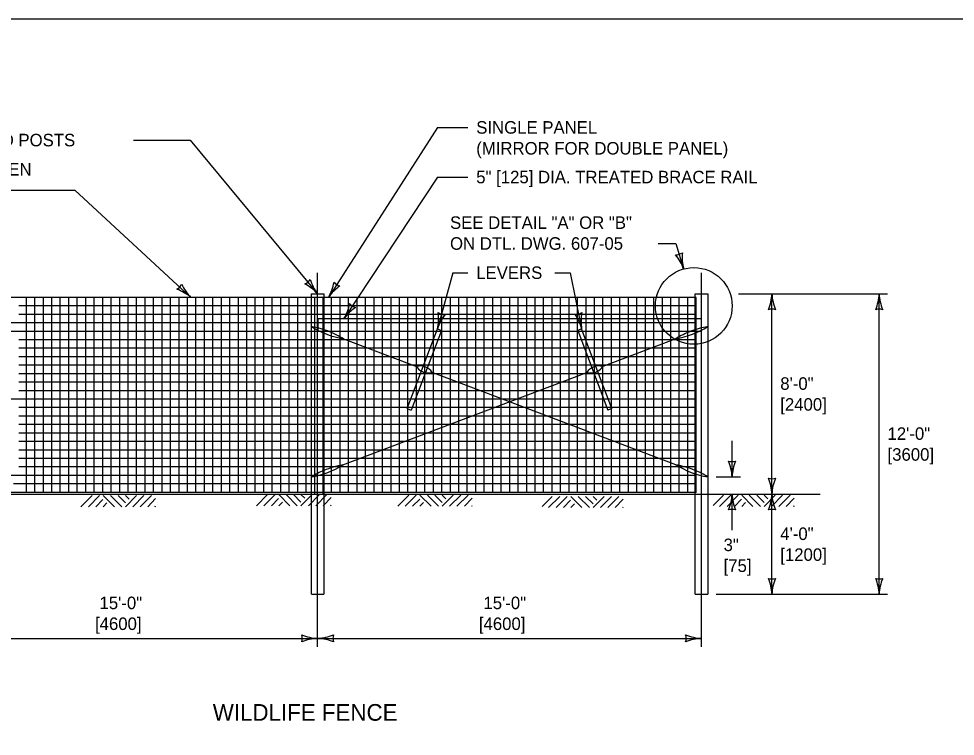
# Model space of a CAD drawing. Extents: x 49991.4 to 50021, y 49987.6 to 50011.4.
# Drawn here: x 50005.896 to 50010.385, y 49995.56 to 49998.999 of the extents above; entities that cross this region are included whole.
import ezdxf

# ---------------------------------------------------------------- set-up
doc = ezdxf.new("R2010")
doc.units = 0
for name, color, linetype in [('Level 1', 7, 'Continuous'), ('Level 2', 7, 'Continuous'), ('Level 3', 7, 'Continuous'), ('Level 4', 7, 'Continuous'), ('Level 5', 7, 'Continuous')]:
    doc.layers.add(name, color=color, linetype=linetype)

msp = doc.modelspace()

# ---------------------------------------------------------------- linework, layer by layer
at = {"layer": 'Level 1'}
for p, q in [((50007.299, 49996.7205), (50007.299, 49997.6806)), ((50007.299, 49997.6806), (50007.359, 49997.6806)), ((50007.359, 49997.6806), (50007.359, 49996.7205)), ((50009.1391, 49997.6806), (50009.1991, 49997.6806)), ((50009.1391, 49996.7205), (50009.1391, 49997.6806)), ((50009.1991, 49997.6806), (50009.1991, 49996.7205)), ((50009.1438, 49997.6633), (50005.1131, 49997.6633)), ((50005.9331, 49996.7285), (50005.9331, 49997.6633)), ((50005.9737, 49996.7285), (50005.9737, 49997.6633)), ((50006.0144, 49996.7285), (50006.0144, 49997.6633)), ((50006.055, 49996.7285), (50006.055, 49997.6633)), ((50006.0957, 49996.7285), (50006.0957, 49997.6633)), ((50006.1363, 49996.7285), (50006.1363, 49997.6633)), ((50006.177, 49996.7285), (50006.177, 49997.6633)), ((50006.2176, 49996.7285), (50006.2176, 49997.6633)), ((50006.2582, 49996.7285), (50006.2582, 49997.6633)), ((50006.2989, 49996.7285), (50006.2989, 49997.6633)), ((50006.3395, 49996.7285), (50006.3395, 49997.6633)), ((50006.3802, 49996.7285), (50006.3802, 49997.6633)), ((50006.4208, 49996.7285), (50006.4208, 49997.6633)), ((50006.4614, 49996.7285), (50006.4614, 49997.6633)), ((50006.5021, 49996.7285), (50006.5021, 49997.6633)), ((50006.5427, 49996.7285), (50006.5427, 49997.6633)), ((50006.5834, 49996.7285), (50006.5834, 49997.6633)), ((50006.624, 49996.7285), (50006.624, 49997.6633)), ((50006.6647, 49996.7285), (50006.6647, 49997.6633)), ((50006.7053, 49996.7285), (50006.7053, 49997.6633)), ((50006.7459, 49996.7285), (50006.7459, 49997.6633)), ((50006.7866, 49996.7285), (50006.7866, 49997.6633)), ((50006.8272, 49996.7285), (50006.8272, 49997.6633)), ((50006.8679, 49996.7285), (50006.8679, 49997.6633)), ((50006.9085, 49996.7285), (50006.9085, 49997.6633)), ((50006.9492, 49996.7285), (50006.9492, 49997.6633)), ((50006.9898, 49996.7285), (50006.9898, 49997.6633)), ((50007.0304, 49996.7285), (50007.0304, 49997.6633)), ((50007.0711, 49996.7285), (50007.0711, 49997.6633)), ((50007.1117, 49996.7285), (50007.1117, 49997.6633)), ((50007.1524, 49996.7285), (50007.1524, 49997.6633)), ((50007.193, 49996.7285), (50007.193, 49997.6633)), ((50007.2336, 49996.7285), (50007.2336, 49997.6633)), ((50007.2743, 49996.7285), (50007.2743, 49997.6633)), ((50007.3149, 49996.7205), (50007.3149, 49997.6633)), ((50007.3556, 49996.7205), (50007.3556, 49997.6633)), ((50007.3962, 49996.7285), (50007.3962, 49997.6633)), ((50007.4369, 49996.7285), (50007.4369, 49997.6633)), ((50007.4775, 49996.7285), (50007.4775, 49997.6633)), ((50007.5181, 49996.7285), (50007.5181, 49997.6633)), ((50007.5588, 49996.7285), (50007.5588, 49997.6633)), ((50007.5994, 49996.7285), (50007.5994, 49997.6633)), ((50007.6401, 49996.7285), (50007.6401, 49997.6633)), ((50007.6807, 49996.7285), (50007.6807, 49997.6633)), ((50007.7214, 49996.7285), (50007.7214, 49997.6633)), ((50007.762, 49996.7285), (50007.762, 49997.6633)), ((50007.8026, 49996.7285), (50007.8026, 49997.6633)), ((50007.8433, 49996.7285), (50007.8433, 49997.6633)), ((50007.8839, 49996.7285), (50007.8839, 49997.6633)), ((50007.9246, 49996.7285), (50007.9246, 49997.6633)), ((50007.9652, 49996.7285), (50007.9652, 49997.6633)), ((50008.0058, 49996.7285), (50008.0058, 49997.6633)), ((50008.0465, 49996.7285), (50008.0465, 49997.6633)), ((50008.0871, 49996.7285), (50008.0871, 49997.6633)), ((50008.1278, 49996.7285), (50008.1278, 49997.6633)), ((50008.1684, 49996.7285), (50008.1684, 49997.6633)), ((50008.2091, 49996.7285), (50008.2091, 49997.6633)), ((50008.2497, 49996.7285), (50008.2497, 49997.6633)), ((50008.2903, 49996.7285), (50008.2903, 49997.6633)), ((50008.331, 49996.7285), (50008.331, 49997.6633)), ((50008.3716, 49996.7285), (50008.3716, 49997.6633)), ((50008.4123, 49996.7285), (50008.4123, 49997.6633)), ((50008.4529, 49996.7285), (50008.4529, 49997.6633)), ((50008.4935, 49996.7285), (50008.4935, 49997.6633)), ((50008.5342, 49996.7285), (50008.5342, 49997.6633)), ((50008.5748, 49996.7285), (50008.5748, 49997.6633)), ((50008.6155, 49996.7285), (50008.6155, 49997.6633)), ((50008.6561, 49996.7285), (50008.6561, 49997.6633)), ((50008.6968, 49996.7285), (50008.6968, 49997.6633)), ((50008.7374, 49996.7285), (50008.7374, 49997.6633)), ((50008.778, 49996.7285), (50008.778, 49997.6633)), ((50008.8187, 49996.7285), (50008.8187, 49997.6633)), ((50008.8593, 49996.7285), (50008.8593, 49997.6633)), ((50008.9, 49996.7285), (50008.9, 49997.6633)), ((50008.9406, 49996.7285), (50008.9406, 49997.6633)), ((50008.9813, 49996.7285), (50008.9813, 49997.6633)), ((50009.0219, 49996.7285), (50009.0219, 49997.6633)), ((50009.0625, 49996.7285), (50009.0625, 49997.6633)), ((50009.1032, 49996.7285), (50009.1032, 49997.6633)), ((50009.1438, 49996.7285), (50009.1438, 49997.6633)), ((50009.1438, 49997.6227), (50005.8964, 49997.6227)), ((50005.9058, 49997.5413), (50005.1225, 49997.5413)), ((50009.1438, 49997.582), (50005.8964, 49997.582)), ((50009.1438, 49997.5414), (50005.9059, 49997.5414)), ((50009.1391, 49997.5607), (50007.359, 49997.5607)), ((50007.3299, 49997.5007), (50005.1131, 49997.5007)), ((50009.1391, 49997.5007), (50007.359, 49997.5007)), ((50007.7587, 49997.1305), (50007.9035, 49997.5125)), ((50007.9222, 49997.5054), (50007.7774, 49997.1234)), ((50007.9035, 49997.5125), (50007.9222, 49997.5054)), ((50008.5945, 49997.5125), (50008.5758, 49997.5054)), ((50008.5758, 49997.5054), (50008.7206, 49997.1234)), ((50008.7393, 49997.1305), (50008.5945, 49997.5125)), ((50009.1438, 49997.4601), (50005.8964, 49997.4601)), ((50007.4529, 49997.4649), (50007.8025, 49997.3323)), ((50009.046, 49997.4653), (50008.6955, 49997.3324)), ((50009.1438, 49997.4194), (50005.8964, 49997.4194)), ((50009.1438, 49997.3788), (50005.8964, 49997.3788)), ((50009.1438, 49997.3382), (50005.8964, 49997.3382)), ((50009.1438, 49997.2975), (50005.8964, 49997.2975)), ((50007.4501, 49996.8602), (50008.6195, 49997.3037)), ((50009.0458, 49996.8611), (50007.8785, 49997.3035)), ((50009.1438, 49997.2569), (50005.8964, 49997.2569)), ((50009.1438, 49997.2162), (50005.8964, 49997.2162)), ((50006.8359, 49997.1756), (50005.1337, 49997.1756)), ((50009.1438, 49997.1756), (50006.8359, 49997.1756)), ((50009.1438, 49997.135), (50005.8964, 49997.135)), ((50009.1438, 49997.0943), (50005.8964, 49997.0943)), ((50007.7587, 49997.1305), (50007.7774, 49997.1234)), ((50008.7393, 49997.1305), (50008.7206, 49997.1234)), ((50009.1438, 49997.0537), (50005.8964, 49997.0537)), ((50009.1438, 49997.013), (50005.8964, 49997.013)), ((50009.1438, 49996.9724), (50005.8964, 49996.9724)), ((50009.1438, 49996.9317), (50005.8964, 49996.9317)), ((50009.1438, 49996.8911), (50005.8964, 49996.8911)), ((50009.1438, 49996.8505), (50005.8964, 49996.8505)), ((50005.9294, 49996.8098), (50005.1463, 49996.8098)), ((50009.1438, 49996.8098), (50005.9295, 49996.8098)), ((50009.1438, 49996.7692), (50005.8709, 49996.7692)), ((50009.1438, 49996.7285), (50005.1131, 49996.7285)), ((50005.1131, 49996.7205), (50009.738, 49996.7205)), ((50006.1948, 49996.6602), (50006.2481, 49996.7134)), ((50006.1948, 49996.6602), (50006.2481, 49996.7134)), ((50006.2303, 49996.6602), (50006.2836, 49996.7134)), ((50006.2303, 49996.6602), (50006.2836, 49996.7134)), ((50006.2658, 49996.6602), (50006.3002, 49996.6945)), ((50006.3546, 49996.6602), (50006.3013, 49996.7134)), ((50006.3901, 49996.6602), (50006.3368, 49996.7134)), ((50006.4078, 49996.6779), (50006.3724, 49996.7134)), ((50006.4078, 49996.6602), (50006.4611, 49996.7134)), ((50006.4078, 49996.6602), (50006.4611, 49996.7134)), ((50006.4256, 49996.6957), (50006.4078, 49996.7134)), ((50006.4434, 49996.6602), (50006.4966, 49996.7134)), ((50006.4434, 49996.6602), (50006.4966, 49996.7134)), ((50006.4788, 49996.6602), (50006.5321, 49996.7134)), ((50006.4788, 49996.6602), (50006.5321, 49996.7134)), ((50006.5144, 49996.6602), (50006.5523, 49996.6992)), ((50006.5144, 49996.6602), (50006.5523, 49996.6992)), ((50007.0362, 49996.6647), (50007.0894, 49996.7179)), ((50007.0362, 49996.6647), (50007.0894, 49996.7179)), ((50007.0717, 49996.6647), (50007.1249, 49996.7179)), ((50007.0717, 49996.6647), (50007.1249, 49996.7179)), ((50007.1072, 49996.6647), (50007.1415, 49996.699)), ((50007.196, 49996.6647), (50007.1427, 49996.7179)), ((50007.2314, 49996.6647), (50007.1782, 49996.7179)), ((50007.2492, 49996.6824), (50007.2137, 49996.7179)), ((50007.2492, 49996.6647), (50007.3024, 49996.7179)), ((50007.2492, 49996.6647), (50007.3024, 49996.7179)), ((50007.267, 49996.7002), (50007.2492, 49996.7179)), ((50007.2847, 49996.6647), (50007.338, 49996.7179)), ((50007.2847, 49996.6647), (50007.338, 49996.7179)), ((50007.3202, 49996.6647), (50007.3735, 49996.7179)), ((50007.3202, 49996.6647), (50007.3735, 49996.7179)), ((50007.3557, 49996.6647), (50007.3936, 49996.7037)), ((50007.3557, 49996.6647), (50007.3936, 49996.7037)), ((50007.7129, 49996.662), (50007.7662, 49996.7152)), ((50007.7129, 49996.662), (50007.7662, 49996.7152)), ((50007.7484, 49996.662), (50007.8017, 49996.7152)), ((50007.7484, 49996.662), (50007.8017, 49996.7152)), ((50007.7839, 49996.662), (50007.8182, 49996.6963)), ((50007.8727, 49996.662), (50007.8194, 49996.7152)), ((50007.9082, 49996.662), (50007.8549, 49996.7152)), ((50007.9259, 49996.6797), (50007.8904, 49996.7152)), ((50007.9259, 49996.662), (50007.9792, 49996.7152)), ((50007.9259, 49996.662), (50007.9792, 49996.7152)), ((50007.9437, 49996.6975), (50007.9259, 49996.7152)), ((50007.9614, 49996.662), (50008.0147, 49996.7152)), ((50007.9614, 49996.662), (50008.0147, 49996.7152)), ((50007.9969, 49996.662), (50008.0502, 49996.7152)), ((50007.9969, 49996.662), (50008.0502, 49996.7152)), ((50008.0324, 49996.662), (50008.0703, 49996.701)), ((50008.0324, 49996.662), (50008.0703, 49996.701)), ((50008.4053, 49996.6611), (50008.4539, 49996.7097)), ((50008.4361, 49996.6564), (50008.4894, 49996.7097)), ((50008.4361, 49996.6564), (50008.4894, 49996.7097)), ((50008.4716, 49996.6564), (50008.5249, 49996.7097)), ((50008.4716, 49996.6564), (50008.5249, 49996.7097)), ((50008.5071, 49996.6564), (50008.5415, 49996.6907)), ((50008.5959, 49996.6564), (50008.5426, 49996.7097)), ((50008.6314, 49996.6564), (50008.5782, 49996.7097)), ((50008.6492, 49996.6742), (50008.6137, 49996.7097)), ((50008.6492, 49996.6564), (50008.7024, 49996.7097)), ((50008.6492, 49996.6564), (50008.7024, 49996.7097)), ((50008.6669, 49996.6919), (50008.6492, 49996.7097)), ((50008.6847, 49996.6564), (50008.7379, 49996.7097)), ((50008.6847, 49996.6564), (50008.7379, 49996.7097)), ((50008.7202, 49996.6564), (50008.7734, 49996.7097)), ((50008.7202, 49996.6564), (50008.7734, 49996.7097)), ((50008.7557, 49996.6564), (50008.7936, 49996.6954)), ((50008.7557, 49996.6564), (50008.7936, 49996.6954)), ((50009.2251, 49996.6666), (50009.2736, 49996.7151)), ((50009.2558, 49996.6618), (50009.3091, 49996.7151)), ((50009.2558, 49996.6618), (50009.3091, 49996.7151)), ((50009.2913, 49996.6618), (50009.3446, 49996.7151)), ((50009.2913, 49996.6618), (50009.3446, 49996.7151)), ((50009.3268, 49996.6618), (50009.3612, 49996.6962)), ((50009.4156, 49996.6618), (50009.3624, 49996.7151)), ((50009.4511, 49996.6618), (50009.3978, 49996.7151)), ((50009.4688, 49996.6796), (50009.4334, 49996.7151)), ((50009.4688, 49996.6618), (50009.5221, 49996.7151)), ((50009.4688, 49996.6618), (50009.5221, 49996.7151)), ((50009.4866, 49996.6974), (50009.4688, 49996.7151)), ((50009.5044, 49996.6618), (50009.5576, 49996.7151)), ((50009.5044, 49996.6618), (50009.5576, 49996.7151)), ((50009.5399, 49996.6618), (50009.5931, 49996.7151)), ((50009.5399, 49996.6618), (50009.5931, 49996.7151)), ((50009.5754, 49996.6618), (50009.6132, 49996.7009)), ((50009.5754, 49996.6618), (50009.6132, 49996.7009)), ((50006.3013, 49996.6602), (50006.3191, 49996.6779)), ((50006.5499, 49996.6602), (50006.5523, 49996.6637)), ((50007.1427, 49996.6647), (50007.1604, 49996.6824)), ((50007.3912, 49996.6647), (50007.3936, 49996.6682)), ((50007.8194, 49996.662), (50007.8372, 49996.6797)), ((50008.068, 49996.662), (50008.0703, 49996.6655)), ((50008.5426, 49996.6564), (50008.5604, 49996.6742)), ((50008.7912, 49996.6564), (50008.7936, 49996.66)), ((50009.3624, 49996.6618), (50009.3801, 49996.6796)), ((50009.6109, 49996.6618), (50009.6132, 49996.6654))]:
    msp.add_line(p, q, dxfattribs=at)
msp.add_lwpolyline([(49999.3835, 49998.9992), (50016.7501, 49998.9992), (50016.7501, 49987.7988), (49999.3835, 49987.7988)], close=True, dxfattribs=at)
for centre, radius, start, end in [((50007.5245, 49997.8858), 0.427, 238.116, 260.3409), ((50007.2277, 49997.1021), 0.427, 58.1709, 68.9895), ((50008.9741, 49997.8861), 0.427, 279.6982, 301.7998), ((50009.271, 49997.1024), 0.427, 111.1243, 121.8042), ((50007.8205, 49997.2654), 0.0694, 33.3818, 105.1082), ((50007.8604, 49997.3705), 0.0694, 213.3818, 240.9544), ((50008.6774, 49997.2655), 0.0694, 74.8918, 146.5866), ((50008.6376, 49997.3706), 0.0694, 299.0896, 326.6182), ((50007.8604, 49997.3705), 0.0694, 257.5334, 285.1082), ((50008.6376, 49997.3706), 0.0694, 254.8644, 282.4666), ((50007.226, 49997.2236), 0.427, 279.8439, 301.6559), ((50007.523, 49996.4395), 0.427, 99.8376, 112.5984), ((50009.2711, 49997.2238), 0.427, 238.1625, 260.2924), ((50008.9737, 49996.4403), 0.427, 67.2012, 80.2676)]:
    msp.add_arc(centre, radius, start, end, dxfattribs=at)
at = {"layer": 'Level 3'}
for p, q in [((50007.9038, 49998.4782), (50007.3807, 49997.6633)), ((50007.9038, 49998.4782), (50008.0492, 49998.4782)), ((50006.4461, 49998.4175), (50006.7173, 49998.4175)), ((50006.7173, 49998.4175), (50007.3289, 49997.6806)), ((50007.9038, 49998.2402), (50007.4546, 49997.5607)), ((50007.9038, 49998.2402), (50008.0492, 49998.2402)), ((50005.5973, 49998.1775), (50006.1655, 49998.1775)), ((50006.1655, 49998.1775), (50006.7217, 49997.6633)), ((50008.9613, 49997.9218), (50009.046, 49997.9218)), ((50009.046, 49997.9218), (50009.0834, 49997.7999)), ((50007.9765, 49997.7818), (50007.9035, 49997.5125)), ((50007.9765, 49997.7818), (50008.0492, 49997.7818)), ((50008.4661, 49997.7818), (50008.5388, 49997.7818)), ((50008.5388, 49997.7818), (50008.5945, 49997.5125)), ((50009.3465, 49997.6806), (50010.0606, 49997.6806)), ((50009.5065, 49996.7203), (50009.5065, 49997.6806)), ((50010.0206, 49996.2405), (50010.0206, 49997.6806)), ((50009.3154, 49996.803), (50009.3154, 49996.9764)), ((50009.2391, 49996.803), (50009.3555, 49996.803)), ((50009.3154, 49996.5471), (50009.3154, 49996.7205)), ((50009.5065, 49996.2405), (50009.5065, 49996.7205)), ((50009.2391, 49996.2405), (50010.0606, 49996.2405)), ((50005.4888, 49996.029), (50007.3291, 49996.029)), ((50007.3291, 49996.029), (50009.1691, 49996.029))]:
    msp.add_line(p, q, dxfattribs=at)
msp.add_circle((50009.132, 49997.6225), 0.1839, dxfattribs=at)
for centre, radius, start, end in [((50009.0458, 49997.9224), 0.0548, 269.2257, 304.9481), ((50008.8644, 49997.7205), 0.233, 19.9142, 39.1641), ((50009.2985, 49997.8564), 0.2223, 174.5429, 194.7264), ((50006.6276, 49997.7503), 0.0548, 299.385, 335.1073), ((50006.8793, 49997.8202), 0.2223, 204.7021, 224.8857), ((50007.2471, 49997.7792), 0.0548, 291.8322, 327.5545), ((50007.1572, 49997.5231), 0.233, 42.5207, 61.7705), ((50007.5057, 49997.8154), 0.2223, 197.1494, 217.3329), ((50007.1787, 49997.7793), 0.233, 330.1447, 349.3946), ((50007.45, 49997.7712), 0.0548, 219.4563, 255.1786), ((50006.5722, 49997.4846), 0.233, 50.0734, 69.3233), ((50007.5628, 49997.5356), 0.2223, 124.7734, 144.957), ((50009.2843, 49997.6897), 0.2223, 337.456, 357.6395), ((50009.7392, 49997.6921), 0.233, 182.8273, 202.0772), ((50009.7984, 49997.6897), 0.2223, 337.456, 357.6395), ((50010.2533, 49997.6921), 0.233, 182.8273, 202.0772), ((50007.2541, 49997.6794), 0.233, 329.3755, 348.6253), ((50007.5253, 49997.6677), 0.0548, 218.687, 254.4093), ((50007.6349, 49997.4306), 0.2223, 124.0042, 144.1877), ((50007.6759, 49997.5623), 0.233, 347.6506, 6.9004), ((50007.9371, 49997.6362), 0.0548, 236.9621, 272.6844), ((50008.5686, 49997.638), 0.0548, 263.8318, 299.5542), ((50008.8139, 49997.5485), 0.2223, 169.149, 189.3325), ((50009.5065, 49997.5524), 0.0548, 72.1388, 107.8612), ((50010.0206, 49997.5524), 0.0548, 72.1388, 107.8612), ((50008.1155, 49997.4455), 0.2223, 142.2793, 162.4628), ((50008.369, 49997.454), 0.233, 14.5203, 33.7702), ((50009.3154, 49996.9312), 0.0548, 252.1388, 287.8612), ((50009.0827, 49996.7915), 0.233, 2.8273, 22.0772), ((50009.5376, 49996.7938), 0.2223, 157.456, 177.6395), ((50009.5065, 49996.8487), 0.0548, 252.1388, 287.8612), ((50009.2738, 49996.709), 0.233, 2.8273, 22.0772), ((50009.7286, 49996.7114), 0.2223, 157.456, 177.6395), ((50009.0933, 49996.7297), 0.2223, 337.456, 357.6395), ((50009.5481, 49996.732), 0.233, 182.8273, 202.0772), ((50009.2843, 49996.7297), 0.2223, 337.456, 357.6395), ((50009.7392, 49996.732), 0.233, 182.8273, 202.0772), ((50009.3154, 49996.5923), 0.0548, 72.1388, 107.8612), ((50009.5065, 49996.5923), 0.0548, 72.1388, 107.8612), ((50009.5065, 49996.3687), 0.0548, 252.1388, 287.8612), ((50009.2738, 49996.229), 0.233, 2.8273, 22.0772), ((50009.7286, 49996.2314), 0.2223, 157.456, 177.6395), ((50010.0206, 49996.3688), 0.0548, 252.1388, 287.8612), ((50009.7878, 49996.2291), 0.233, 2.8273, 22.0772), ((50010.2427, 49996.2314), 0.2223, 157.456, 177.6395), ((50007.3381, 49996.2511), 0.2223, 247.456, 267.6395), ((50007.2008, 49996.029), 0.0548, 342.1388, 17.8612), ((50007.3405, 49995.7963), 0.233, 92.8273, 112.0772), ((50007.3175, 49996.2617), 0.233, 272.8273, 292.0772), ((50007.3198, 49995.8068), 0.2223, 67.456, 87.6395), ((50007.4572, 49996.029), 0.0548, 162.1388, 197.8612), ((50009.1782, 49996.2511), 0.2223, 247.456, 267.6395), ((50009.0408, 49996.029), 0.0548, 342.1388, 17.8612), ((50009.1806, 49995.7963), 0.233, 92.8273, 112.0772)]:
    msp.add_arc(centre, radius, start, end, dxfattribs=at)
at = {"layer": 'Level 4'}
for p, q in [((50007.359, 49997.5607), (50007.3299, 49997.5607)), ((50007.3299, 49997.5607), (50007.3299, 49997.5007)), ((50009.1667, 49997.5607), (50009.1391, 49997.5607)), ((50009.1667, 49997.5607), (50009.1667, 49997.5007)), ((50007.359, 49997.5007), (50007.3299, 49997.5007)), ((50009.1667, 49997.5007), (50009.1391, 49997.5007)), ((50007.299, 49996.2405), (50007.299, 49996.7205)), ((50007.359, 49996.7205), (50007.359, 49996.2405)), ((50009.1391, 49996.2405), (50009.1391, 49996.7205)), ((50009.1991, 49996.7205), (50009.1991, 49996.2405)), ((50007.299, 49996.2405), (50007.359, 49996.2405)), ((50009.1391, 49996.2405), (50009.1991, 49996.2405))]:
    msp.add_line(p, q, dxfattribs=at)
for centre, radius, start, end in [((50007.227, 49997.1024), 0.427, 68.8868, 80.2887), ((50009.271, 49997.1024), 0.427, 99.6942, 111.1138), ((50007.8604, 49997.3705), 0.0694, 240.9565, 257.5334), ((50008.6376, 49997.3706), 0.0694, 282.4755, 299.0523), ((50007.5231, 49996.4395), 0.427, 112.6049, 121.6559), ((50008.9741, 49996.4401), 0.427, 58.198, 67.2602)]:
    msp.add_arc(centre, radius, start, end, dxfattribs=at)
at = {"layer": 'Level 5'}
for p, q in [((50007.329, 49995.989), (50007.329, 49997.7806)), ((50009.1691, 49995.989), (50009.1691, 49997.7806))]:
    msp.add_line(p, q, dxfattribs=at)

# ---------------------------------------------------------------- texts
at = {"layer": 'Level 2'}
for s, height, p in [('SINGLE PANEL', 0.06, (50008.0892, 49998.4482)), ('7" [180] DIA. TREATED WOOD POSTS', 0.060003, (50004.743, 49998.3875)), ('(MIRROR FOR DOUBLE PANEL)', 0.06, (50008.0892, 49998.3482)), ('ASTM 2096-12-12 1/2 [12.5] WOVEN', 0.06, (50004.62, 49998.2475)), ('5" [125] DIA. TREATED BRACE RAIL', 0.060003, (50008.0892, 49998.2102)), ('SEE DETAIL "A" OR "B" ', 0.060003, (50007.9636, 49997.9918)), ('ON DTL. DWG. 607-05', 0.060003, (50007.9636, 49997.8918)), ('LEVERS', 0.06, (50008.0892, 49997.7518)), ('8\'-0"', 0.06, (50009.5465, 49997.2204)), ('[2400]', 0.06, (50009.5465, 49997.1204)), ('12\'-0"', 0.06, (50010.0606, 49996.9805)), ('[3600]', 0.06, (50010.0606, 49996.8805)), ('4\'-0"', 0.06, (50009.5465, 49996.5004)), ('3"', 0.06, (50009.2748, 49996.4471)), ('[1200]', 0.06, (50009.5465, 49996.4004)), ('[75]', 0.06, (50009.2748, 49996.3471)), ('15\'-0"', 0.06, (50006.2836, 49996.169)), ('15\'-0"', 0.06, (50008.1238, 49996.169)), ('[4600]', 0.06, (50006.2619, 49996.069)), ('[4600]', 0.06, (50008.102, 49996.069)), ('WILDLIFE FENCE', 0.08, (50006.8264, 49995.634))]:
    msp.add_text(s, height=height, dxfattribs=at).set_placement(p)

doc.saveas('drawing.dxf')
